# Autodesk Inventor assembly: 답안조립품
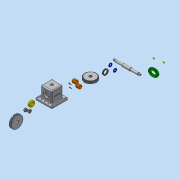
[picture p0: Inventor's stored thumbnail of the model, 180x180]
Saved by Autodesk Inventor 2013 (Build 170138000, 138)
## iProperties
Created: 2018-11
Part Number: 답안조립품
Document SubType Name: Assembly
Designer: dgall
Author: dgall
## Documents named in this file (13)
- C:\Users\dgall\Desktop\481107V1015\답안조립품.iam
- C:\Users\dgall\Desktop\481107V1015\V벨트풀리.ipt
- C:\Users\dgall\Desktop\481107V1015\너트 M12x1.25.ipt
- C:\Users\dgall\Desktop\481107V1015\베어링 6203.ipt
- C:\Users\dgall\Desktop\481107V1015\본체.ipt
- C:\Users\dgall\Desktop\481107V1015\볼트 M4.ipt
- C:\Users\dgall\Desktop\481107V1015\부시.ipt
- C:\Users\dgall\Desktop\481107V1015\스퍼기어.ipt
- C:\Users\dgall\Desktop\481107V1015\오일 실 26 38 8.ipt
- C:\Users\dgall\Desktop\481107V1015\와셔 12x24.ipt
- C:\Users\dgall\Desktop\481107V1015\축.ipt
- C:\Users\dgall\Desktop\481107V1015\커버.ipt
- C:\Users\dgall\Desktop\481107V1015\키 5x5x12.ipt
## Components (1 placed, 1 different names)
1. V벨트풀리:1
